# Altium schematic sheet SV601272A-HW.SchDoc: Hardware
size 431 x 279 mm; Date: Not shown in title block; ApprovedBy: Not shown in title block; CheckedBy: Not shown in title block; Author: Not shown in title block; CompanyName: Not shown in title block; Engineer: Not shown in title block; Organization: Not shown in title block; Address1: Not shown in title block; Address2: Not shown in title block; Address3: Not shown in title block; Address4: Not shown in title block; DocumentNumber: 2; Revision: Use project parameter SCH_Rev; SheetNumber: 2; SheetTotal: 11; PageSetup: Record=PageOptions¦CenterHorizontal=True¦CenterVertical=True¦PrintScale=1.00¦XCorrection=1.00¦YCorrection=1.00¦PrintKind=0¦BorderSize=5000000¦LeftOffset=0¦BottomOffset=0¦Orientation=2¦PaperLength=1000¦PaperWidth=1000¦Scale=100¦PaperSource=15¦PrintQuality=600¦MediaType=1¦DitherType=10¦PaperKind=Letter¦PrintScaleMode=1
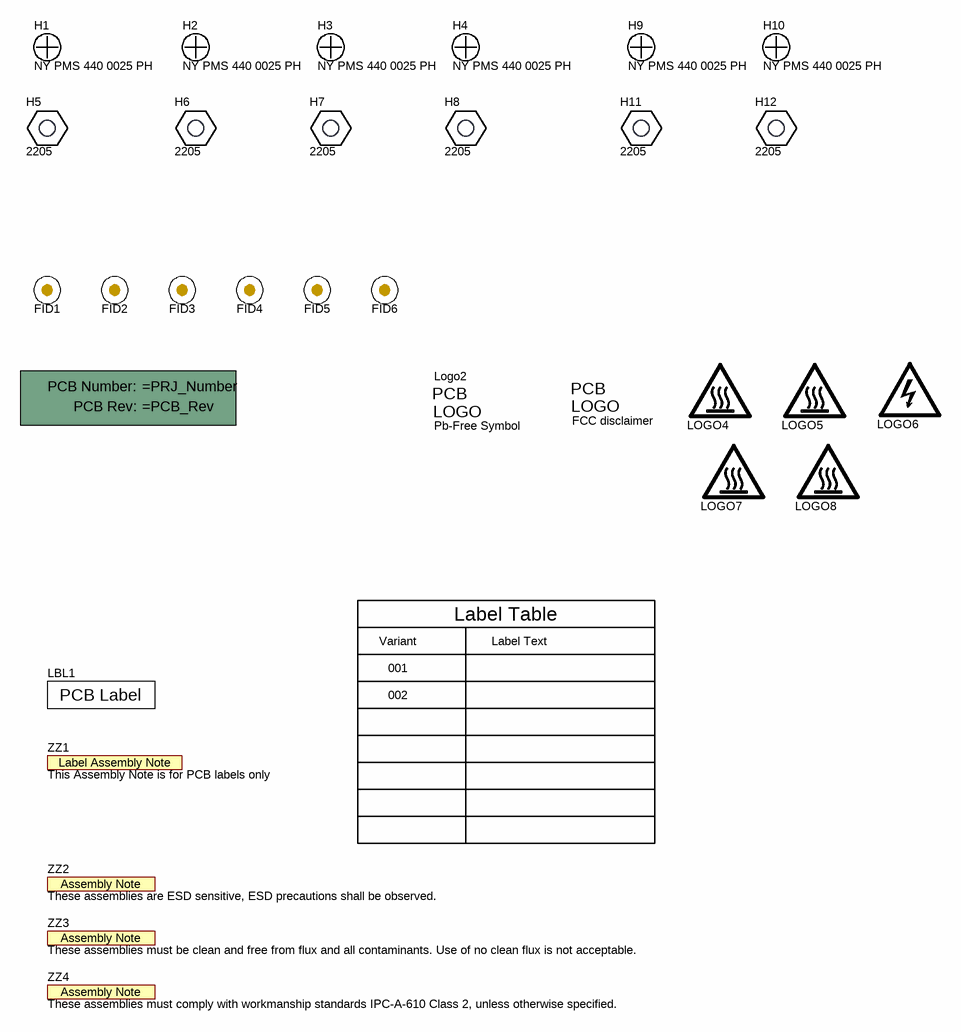
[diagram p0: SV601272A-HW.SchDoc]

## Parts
!PCB1  Printed Circuit Board  (value not drawn)  (mechanical)
FID1  Fiducial  [Fiducial10-20]  (value not drawn)
FID2  Fiducial  [Fiducial10-20]  (value not drawn)
FID3  Fiducial  [Fiducial10-20]  (value not drawn)
FID4  Fiducial  [Fiducial10-20]  (value not drawn)
FID5  Fiducial  [Fiducial10-20]  (value not drawn)
FID6  Fiducial  [Fiducial10-20]  (value not drawn)
H1  NY PMS 440 0025 PH  [NY PMS 440 0025 PH]
H2  NY PMS 440 0025 PH  [NY PMS 440 0025 PH]
H3  NY PMS 440 0025 PH  [NY PMS 440 0025 PH]
H4  NY PMS 440 0025 PH  [NY PMS 440 0025 PH]
H5  2205  [KEYSTONE_2205]
H6  2205  [KEYSTONE_2205]
H7  2205  [KEYSTONE_2205]
H8  2205  [KEYSTONE_2205]
H9  NY PMS 440 0025 PH  [NY PMS 440 0025 PH]
H10  NY PMS 440 0025 PH  [NY PMS 440 0025 PH]
H11  2205  [KEYSTONE_2205]
H12  2205  [KEYSTONE_2205]
LBL1  (no value)  [Label_1250x250]
Logo2  Pb-Free Symbol  [Pb-Free_Overlay_Medium]  (no BOM)
Logo3  FCC disclaimer  [FCC_disclaimer_stacked]  (no BOM)
LOGO4  CAUTION HOT SURFACE  [IEC_HotSurface_Small]  (value not drawn)  (no BOM)
LOGO5  CAUTION HOT SURFACE  [IEC_HotSurface_Small]  (value not drawn)  (no BOM)
LOGO6  DANGER HIGH VOLTAGE  [IEC_HighVoltage_Small]  (value not drawn)  (no BOM)
LOGO7  CAUTION HOT SURFACE  [IEC_HotSurface_Small]  (value not drawn)  (no BOM)
LOGO8  CAUTION HOT SURFACE  [IEC_HotSurface_Small]  (value not drawn)  (no BOM)
ZZ1  This Assembly Note is for PCB labels only  [AssemblyNoteLabel]  (no BOM)
ZZ2  These assemblies are ESD sensitive, ESD precautions shall be observed.  [AssemblyNote]  (no BOM)
ZZ3  These assemblies must be clean and free from flux and all contaminants. Use of no clean flux is not acceptable.  [AssemblyNote]  (no BOM)
ZZ4  These assemblies must comply with workmanship standards IPC-A-610 Class 2, unless otherwise specified.  [AssemblyNote]  (no BOM)

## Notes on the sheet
- Variant
- Label Table
- Label Text
- 001
- 002

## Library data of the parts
!PCB1 = PCB: Manufacturer: Any; SymbolCreator: a0412235
FID1-FID6 = Fiducial: Fiducial mark.  There is nothing to buy or mount.; SymbolCreator: codlsc
H1-H4 H9 H10 = NY PMS 440 0025 PH: Machine Screw, Round, #4-40 x 1/4, Nylon, Philips panhead; Manufacturer: B&F Fastener Supply; CompType: Hardware; SymbolCreator: codlsc; U/M: EA
H5-H8 H11 H12 = 2205: Standoff, Hex, 1"L #4-40 Aluminum; Manufacturer: Keystone; SymbolCreator: a0412235
LBL1 = THT-13-457-10: Thermal Transfer Printable Labels, 1.250" W x 0.250" H - 10,000 per roll; Manufacturer: Brady; SymbolCreator: a0412235; CompType: Label
Logo2 = Pb-Free: SymbolCreator: a0412235
Logo3 = FCC_disclaimer: SymbolCreator: codlsc
LOGO4 LOGO5 LOGO7 LOGO8 = IEC_HotSurface: IEC 61010-1 Hot Surface Warning; SymbolCreator: a0412235
LOGO6 = IEC_HighVoltage: IEC 61010-1 High Voltage Warning; SymbolCreator: a0412235
ZZ1 = AssemblyNoteLabel: SymbolCreator: a0412235
ZZ2-ZZ4 = AssemblyNote: SymbolCreator: codlsc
